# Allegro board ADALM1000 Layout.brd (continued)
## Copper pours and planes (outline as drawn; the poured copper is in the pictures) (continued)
GND on TOP: 47.79,2.17 55.66,2.17 55.66,4.45 54.01,4.45 52.1,6.36 52.1,6.61 53.12,6.61 53.25,6.74 53.25,7.63 54.52,8.9 55.66,8.9 55.66,10.17 51.47,10.17 51.47,11.18 51.98,11.69 55.41,11.69 55.66,11.95 55.66,12.96 49.56,12.96 49.56,9.66 46.9,6.99 48.42,6.99 48.8,6.61 48.8,5.21 50.96,5.21 50.96,3.69 50.58,3.31 47.79,3.31
GND on TOP: 8.8,40.9 8.8,38.74 6,38.74 6,40.9
GND on TOP: outline of 258 points within -6.95,0.9 79.41,53.22 ; 16 cut-outs
GND on BOTTOM: 17.37,0.9 17.37,4.07 15.85,4.07 15.85,5.09 7.21,5.09 7.21,5.34 6.19,5.34 6.19,6.61 5.94,6.61 5.94,5.34 4.67,5.34 4.67,5.09 4.35,5.09 4.35,4.07 2.19,4.07 2.19,3.06 -2.21,3.06 -3.95,5.49 -6.82,4.65 -6.93,4.62 -7,4.71 -7,19.31 -6.38,19.31 -6.38,19.95 -5.81,19.95 -5.43,20.33 -5.43,20.84 -5.05,21.22 -1.11,21.22 -0.47,21.85 -0.47,32.27 -1.11,32.9 -7,32.9 -7,37.98 3.91,37.98 6.45,40.52 17.24,40.52 20.1,43.38 20.1,47.82 21.05,48.78 32.17,48.78 32.8,48.14 40.42,48.14 40.42,40.65 34.07,34.3 16.29,34.3 15.78,34.81 10,34.81 5.43,30.23 5.43,17.79 6.26,16.96 6.26,6.36 7.15,5.47 21.18,5.47 21.18,3.25 25.69,3.25 25.69,3.63 27.59,1.72 35.34,1.72 35.34,4.33 42.2,4.33 44.36,2.17 69.63,2.17 70.27,2.8 70.27,3.56 69.12,4.71 69.12,8.9 69.63,9.41 78.52,9.41 79.16,8.77 79.16,0.9 ; 1 cut-out
GND on L2_GND: 6.26,0.85 6.26,0.85 -4.79,0.85 -7,3.06 -7,21.52 -7.41,21.52 -7.41,23.6 -7.1,23.6 -6.35,23.93 -6.06,24.7 -6.38,25.43 -7.1,25.76 -7.41,25.76 -7.41,28.35 -7.1,28.35 -6.35,28.68 -6.06,29.45 -6.38,30.18 -7.1,30.51 -7.41,30.51 -7.41,32.59 -7,32.59 -7,51.09 -4.79,53.3 23.97,53.3 23.97,41.35 25.44,41.35 25.62,41.53 25.62,41.79 25.44,41.98 24.61,41.98 24.61,53.3 38.07,53.3 38.07,49.02 38.26,48.84 38.52,48.84 38.71,49.02 38.71,53.3 77.22,53.3 79.43,51.09 79.43,3.06 77.22,0.85 ; 5 cut-outs
GND on L3_VDD: 24.42,37.66 24.42,53.3 39.02,53.3 39.02,37.66
VCC on BOTTOM: 11.21,46.87 11.21,44.97 1.05,44.97 1.05,43.06 -2.12,43.06 -3.39,44.33 -3.39,46.87
UNNAMED_2_ADM1178_I544_SENSE on TOP: 13.5,47.12 13.5,49.28 20.61,49.28 20.61,47.12
UNNAMED_2_ADM7171_I450_EN on TOP: 39.72,49.47 39.72,50.62 41.49,50.62 41.49,49.47
UNNAMED_2_ADP1614_I395_SW1 on TOP: 29.75,44.84 28.74,43.82 28.74,42.93 32.17,42.93 32.17,44.71 32.42,44.97 34.96,44.97 35.23,45.08 35.34,45.35 35.34,47.12 35.23,47.39 34.96,47.51 30.13,47.51 29.86,47.39 29.75,47.12
UNNAMED_2_ADP2442_I24_BST on TOP: 6.77,45.22 6.77,44.58 7.4,43.95 8.92,43.95 9.05,43.82 9.05,41.66 11.34,41.66 11.34,44.46 10.96,44.84 8.04,44.84 7.65,45.22
UNNAMED_2_ADP2442_I24_PGND on TOP: 5.24,44.46 5.24,43.57 4.99,43.31 3.59,43.31 2.57,42.3 2.57,40.65 4.1,40.65 4.1,37.6 2.19,37.6 2.19,38.23 0.54,38.23 0.54,43.95 2.07,43.95 2.32,44.2 4.73,44.2 4.99,44.46
UNNAMED_2_ADP2442_I24_SW on TOP: 5.75,43.06 5.75,38.49 9.05,38.49 9.05,40.65 11.34,40.65 11.34,38.11 9.56,36.33 5.62,36.33 4.48,37.47 4.48,42.04 5.5,43.06
UNNAMED_2_ADR38X_I459_VOUT on TOP: 59.6,49.41 61.88,49.41 63.03,50.55 63.03,52.08 60.49,52.08 59.6,51.19
UNNAMED_2_CAP_I419_N1 on TOP: 32.55,44.08 32.55,40.77 34.32,40.77 34.71,40.39 38.39,40.39 38.75,40.54 38.9,40.9 38.9,43.95 38.75,44.31 38.39,44.46 32.93,44.46
UNNAMED_2_CAP_I439_N1 on TOP: 28.16,42.81 28.16,44.2 27.72,44.65 27.72,46.87 26.96,47.63 26.96,47.89 29.12,47.89 29.3,47.81 29.37,47.63 29.37,45.03 28.55,44.2 28.55,42.81
UNNAMED_2_CN5P4PSHLD_I378_GND1 on TOP: -2.63,31.5 -2.63,28.96 -2.38,28.71 -0.47,28.71 -0.47,31.88 -2.25,31.88
UNNAMED_2_CN5P4PSHLD_I378_GND1 on BOTTOM: -7.41,21.72 -7.41,23.6 -7.1,23.6 -6.02,24.68 -7.1,25.76 -7.41,25.76 -7.41,28.35 -7.13,28.35 -6.05,29.43 -7.13,30.51 -7.41,30.51 -7.41,32.39 -1.36,32.39 -0.98,32.01 -0.98,22.11 -1.36,21.72
UNNAMED_2_CN5P4PSHLD_I378_GND1 on L3_VDD: -7.41,21.53 -7.41,23.6 -7.1,23.6 -6.35,23.93 -6.06,24.7 -6.38,25.43 -7.1,25.76 -7.41,25.76 -7.41,28.35 -7.1,28.35 -6.35,28.68 -6.06,29.45 -6.38,30.18 -7.1,30.51 -7.41,30.51 -7.41,32.58 -1.81,32.58 -1.81,28.65 -2.57,28.65 -2.57,23.44 -3.33,23.44 -3.33,21.53
UNNAMED_2_RES_I435_N2 on TOP: 21.37,52.33 21.01,52.18 20.86,51.82 20.86,47.12 23.28,47.12 23.45,47.2 23.53,47.38 23.53,47.89 23.64,48.16 23.91,48.27 27.59,48.27 27.85,48.52 29.37,48.52 29.88,48.01 34.96,48.01 35.23,48.12 35.34,48.39 35.34,51.82 35.19,52.18 34.83,52.33
VUSB on TOP: 13.5,49.79 13.5,51.57 16.67,51.57 16.67,49.79
VUSB on L3_VDD: -7,17.98 -7,20.9 -2.7,20.9 -2.7,22.8 -1.93,22.8 -1.93,28.01 -1.17,28.01 -1.17,33.22 -7,33.22 -7,51.09 -4.79,53.3 18.07,53.3 18.07,44.65 15.21,44.65 15.21,49.73 3.15,49.73 3.15,41.79 4.73,41.79 4.73,26.23 -0.03,26.23 -0.03,17.98

Small or netless copper shapes (teardrops, artwork), in the pictures only: 1 on TOP

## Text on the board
Ref Des/Silkscreen Bottom: 08-037760 REV F Z | SECONDARY SIDE | CAN ICES-3(B)/NMB-3(B) | GND | BIN | AIN | CH A | 2.5V | 5.0V | CH B | 3.3V | PIO 3 | PIO 2 | PIO 1 | PIO 0 | SOURCE | MEASURE | CH | CH IN | V | A | Vs | Is | 1M | ADALM1000
User.Comments: SEE DETAIL A | 3.    DS1, DS2 AND DS3 ARE REVERSE MOUNT LEDS. | 3.    PIN 1 AND PIN 2 OF P6 SHOULD BE SHORTED BY SOLDERING UPON ASSEMBLY.
Ref Des/Silkscreen Top: PRIMARY SIDE | 08-037760 REV F Z
DIMENSION: 1.056 | 1.039 | 1.021 | -.157 | 2.048 | .869 | .852 | .834 | "0" | 3.543 | REF | .018 R | CUT-OUT | 2 PLACES | 3 PLACES | 2.205 | .157 R | -.092 | 3.386 | DIA MAX
PAGE_OUTLINE: B | C | D | D-2 | E | F | ECR-046615 | ECR-047049 | ECR-048787 | ECR-050824 | ECR-054020 | ECR-064688 | 01JUL14 | 15SEP14 | 30OCT14 | 06JAN15 | 02JUL16 | 12SEP17 | I.D. | M.B. | CUSTOMER EVALUATION Z | AD7689
User.11: DETAIL A
User.15: RoHS COMPLIANCE; | IMPEDANCE CONTROLLED SPACING = 10MILS | HOMOGENOUS MATERIALS IN THIS BOARD SHALL BE COMPLIANT | WITH THE EU RoHS DIRECIVE 2002/95/EC. | SECONDARY SILKSCREEN | 2
User.17: 08-      -07 | L2 GND
User.18: 08-      -08 | L3 VDD
User.19: 08-      -09 | L4 SIG
User.20: 08-      -10 | L5 GND
User.24: PER NOTES/STACKUP | LAYERED MATERIAL | IMMERSION GOLD | 0.063" THICK | ELECTROLESS | NICKEL
User.28: 0.063" THICK | LAYERED MATERIAL | PER NOTES/STACKUP | ELECTROLESS | NICKEL | IMMERSION GOLD
User.45: FIGURE | SIZE | 10.0 | 40.0 | 35.44 | 125.0 | 41.0x26.0 | 51.0x28.0 | FINISHED HOLES IN MILS | ALL UNITS ARE IN MILS | PLATED | NON-PLATED | QTY | 461 | 14 | 2 | 4 | TOLERANCE/NOTES
